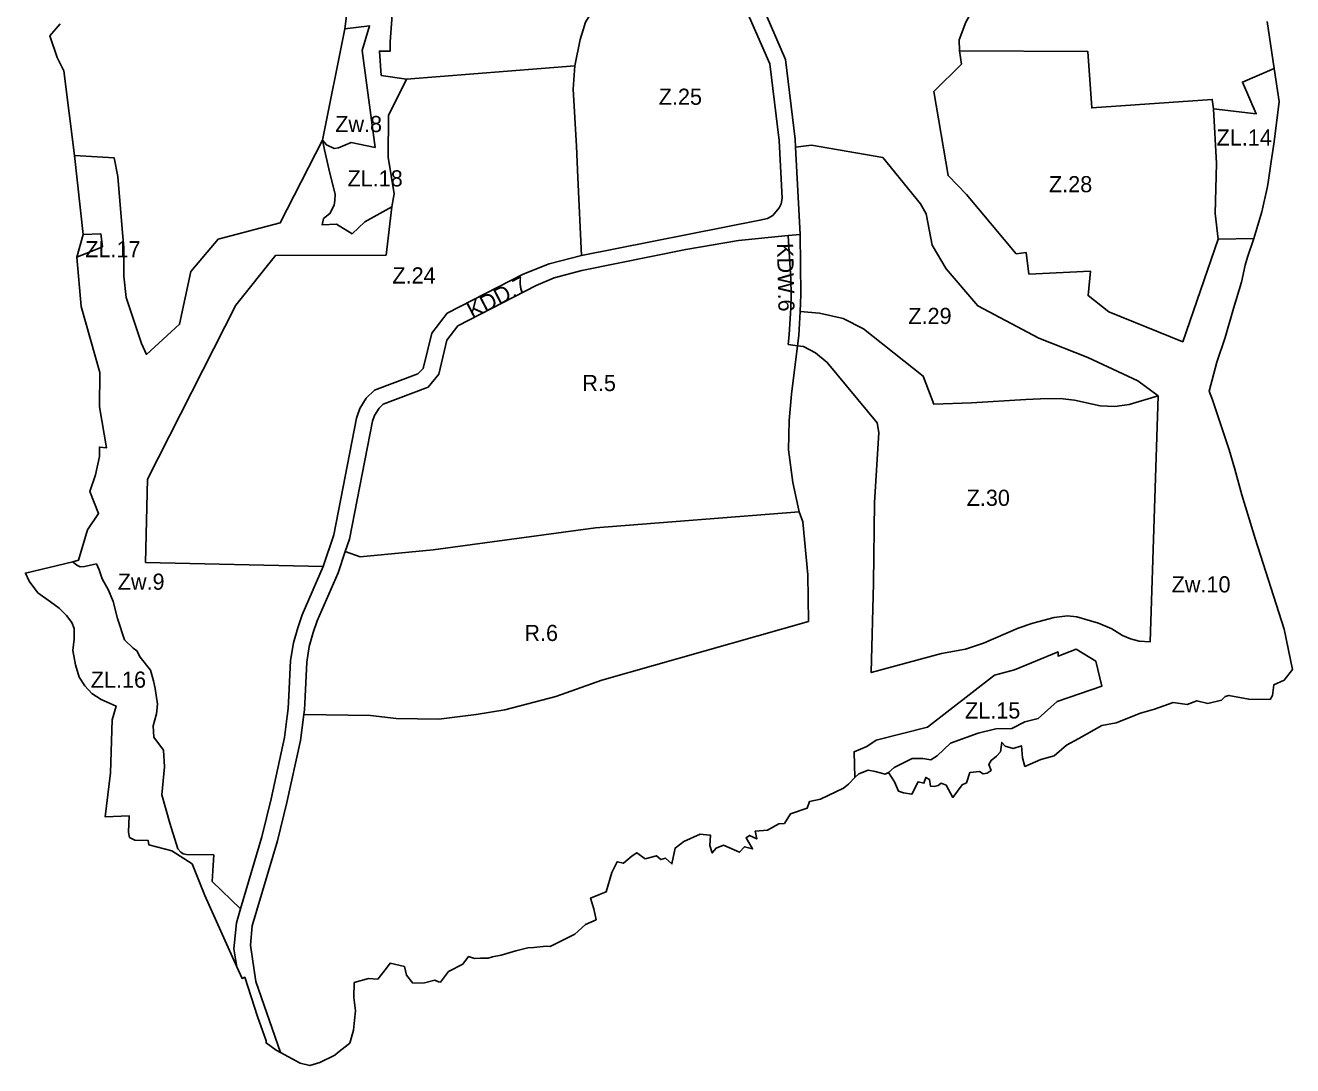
# Model space of a CAD drawing. Extents: x 7425478 to 7427982, y 5538517 to 5541171.
# Drawn here: x 7425675 to 7426459, y 5538517 to 5539161 of the extents above; entities that cross this region are included whole.
import ezdxf

# ---------------------------------------------------------------- set-up
doc = ezdxf.new("R2010")
doc.units = 0
doc.layers.add('linie_rozgraniczajace', color=7, linetype='Continuous')
doc.layers.add('oznaczenia_przeznaczen', color=7, linetype='Continuous')

msp = doc.modelspace()

# ---------------------------------------------------------------- linework, layer by layer
at = {"layer": 'linie_rozgraniczajace'}
for p, q in [((7425859.18, 5539089.77), (7425872.91, 5539158.79)), ((7425911.14, 5539127.51), (7426015.22, 5539135.71)), ((7426154.66, 5539031.49), (7426151.82, 5539085.48)), ((7426147.11, 5539030.69), (7426154.66, 5539031.49)), ((7426435.23, 5539028.98), (7426413.26, 5539028.54)), ((7425936.26, 5538982.64), (7425926.73, 5538970.31)), ((7425926.73, 5538970.31), (7425921.32, 5538948.42)), ((7425942.82, 5538974.77), (7425935.98, 5538965.92)), ((7425935.98, 5538965.92), (7425931.11, 5538944.9)), ((7426152.98, 5538962.54), (7426147.13, 5538963.32)), ((7425880.19, 5538917.77), (7425866.07, 5538845.42)), ((7425890, 5538915.88), (7425875.76, 5538842.86)), ((7426027.99, 5538849.76), (7426153.92, 5538859.85)), ((7426156.21, 5538853.5), (7426159.35, 5538820.71)), ((7425859.47, 5538825.87), (7425866.07, 5538845.42)), ((7425873.21, 5538835.3), (7425875.76, 5538842.86)), ((7425859.47, 5538825.87), (7425749.66, 5538828.37)), ((7425859.47, 5538825.87), (7425846.55, 5538796)), ((7426031.95, 5538755.64), (7426159.86, 5538791.87)), ((7425804.34, 5538589.28), (7425806.18, 5538578.12)), ((7425814.58, 5538591.46), (7425817.8, 5538569.09))]:
    msp.add_line(p, q, dxfattribs=at)
for points in [[(7425911.14, 5539127.51), (7425895.48, 5539129.82), (7425894.29, 5539144.9), (7425900.95, 5539144.83), (7425900.94, 5539150.62), (7425903, 5539178.71), (7425906.76, 5539195.32), (7425905.22, 5539195.17), (7425905.53, 5539201.35), (7425907.43, 5539202.47), (7425907.2, 5539235.15), (7425911.58, 5539260.65), (7425914.39, 5539273.74), (7425914.83, 5539278)], [(7425872.91, 5539158.79), (7425876.32, 5539186.72), (7425886.84, 5539193.05), (7425892.12, 5539214.17), (7425886.62, 5539235.46), (7425884.02, 5539237.65), (7425887.14, 5539253.37)], [(7426019.32, 5539018.32), (7426129.7, 5539040.2), (7426134.42, 5539041.34), (7426137.76, 5539043.2), (7426141.67, 5539047.91), (7426142.89, 5539050.48), (7426143.53, 5539053.88), (7426141.59, 5539089.62), (7426135.87, 5539137), (7426107.86, 5539201.24), (7426107.49, 5539204.41)], [(7426015.22, 5539135.71), (7426018.42, 5539151.99), (7426020.29, 5539158.01), (7426021.79, 5539162.83), (7426028.53, 5539173.75), (7426030.01, 5539177.46), (7426037.1, 5539195.25), (7426056.56, 5539197.78)], [(7426151.82, 5539085.48), (7426151.56, 5539090.49), (7426145.63, 5539139.65), (7426133.53, 5539167.33)], [(7426253.18, 5539145.1), (7426253, 5539151.86), (7426257.18, 5539162.75), (7426261.32, 5539170.23)], [(7426443.46, 5539163.33), (7426447.85, 5539134.04), (7426450.91, 5539113.67), (7426447.92, 5539088.66), (7426445.9, 5539076.62), (7426444.32, 5539064.93), (7426443.79, 5539061.12), (7426440.3, 5539045.47), (7426435.23, 5539028.98), (7426431.35, 5539017.43), (7426429.99, 5539012.34), (7426427.7, 5539001.83), (7426422.65, 5538985.66), (7426417.55, 5538967.6), (7426412.39, 5538952.44), (7426407.67, 5538934.46), (7426409.7, 5538929.17), (7426420.11, 5538898.03), (7426423.47, 5538886.22), (7426427.76, 5538870.31), (7426436.04, 5538843.26), (7426454.02, 5538787.09), (7426459.29, 5538762.25), (7426454.03, 5538755.63), (7426447.57, 5538752.58), (7426446.91, 5538746.11), (7426445.33, 5538743.66), (7426432.13, 5538743.75), (7426419.89, 5538746.15), (7426417.48, 5538745.41), (7426415.23, 5538743.28), (7426406.81, 5538741.13), (7426400.07, 5538742.8), (7426394.04, 5538740.55), (7426385.47, 5538741.75), (7426373.9, 5538737.61), (7426365.15, 5538735.14), (7426350.18, 5538729.16), (7426341.17, 5538727.45), (7426326.95, 5538719.43), (7426319.39, 5538715.34), (7426311.77, 5538708.71), (7426303.46, 5538706.39), (7426293.63, 5538702.2), (7426292.22, 5538707.54), (7426291.64, 5538714.86), (7426286.28, 5538713.2), (7426281.52, 5538714.62), (7426279.31, 5538717.05), (7426278.53, 5538711.14), (7426276.03, 5538708.57), (7426272.83, 5538705.92), (7426271.28, 5538703.42), (7426272.77, 5538699.68), (7426270.35, 5538697.94), (7426267.85, 5538697.69), (7426265.48, 5538698.95), (7426259.49, 5538698.37), (7426257.47, 5538692.04), (7426254.79, 5538690.79), (7426249.11, 5538683.04), (7426245.03, 5538690.51), (7426241.78, 5538691.91), (7426240.01, 5538690.47), (7426237.45, 5538689.8), (7426235.3, 5538689.88), (7426234.54, 5538694.15), (7426232.26, 5538695.33), (7426231.17, 5538691.81), (7426227.56, 5538692.56), (7426223.72, 5538685.04), (7426218.6, 5538685.86), (7426215.42, 5538686.88), (7426213.03, 5538692.56), (7426209.32, 5538698.44), (7426207.21, 5538697.45), (7426200.96, 5538699.01), (7426196.67, 5538699.95), (7426190.85, 5538697.62), (7426188.45, 5538695.35), (7426184.6, 5538691.16), (7426181.32, 5538688.82), (7426167.11, 5538681.94), (7426160.43, 5538680.55), (7426158.91, 5538676.31), (7426148.66, 5538672.8), (7426144.9, 5538666.82), (7426141.41, 5538666.58), (7426134.36, 5538662.81), (7426126.83, 5538662.02), (7426127.74, 5538657.3), (7426123.36, 5538659.45), (7426121.17, 5538658.01), (7426125.12, 5538651.14), (7426120.22, 5538652.5), (7426116.98, 5538649.08), (7426107.25, 5538653.46), (7426102.61, 5538651.59), (7426100.25, 5538648.6), (7426098.67, 5538653.28), (7426099.1, 5538659.71), (7426098.52, 5538659.7), (7426092.74, 5538660.26), (7426082.71, 5538655.67), (7426077.21, 5538651.62), (7426075.22, 5538641.79), (7426071.22, 5538645.46), (7426068.34, 5538644.55), (7426065.64, 5538646.9), (7426058.63, 5538644.95), (7426053.64, 5538648.74), (7426050.64, 5538646.83), (7426045.22, 5538642.28), (7426041.38, 5538643.23), (7426038.19, 5538636.52), (7426034.61, 5538624.66), (7426030.42, 5538622.81), (7426024.92, 5538620.72), (7426026.96, 5538614.06), (7426028.31, 5538607.27), (7426021.88, 5538604.37), (7426015.15, 5538598.31), (7426000.04, 5538590.75), (7425997.47, 5538590.85), (7425989.86, 5538590.05), (7425986.13, 5538590), (7425978.71, 5538587.95), (7425969.55, 5538585.41), (7425964.23, 5538584.42), (7425961.49, 5538583.47), (7425956.88, 5538583.51), (7425953.16, 5538583.39), (7425949.49, 5538584.59), (7425945.84, 5538579.76), (7425937.15, 5538575.35), (7425932.11, 5538568.74), (7425930.87, 5538568.76), (7425928.54, 5538569.87), (7425922.1, 5538568.19), (7425915.08, 5538568.1), (7425911.07, 5538572.97), (7425909.75, 5538578.29), (7425900.86, 5538580.37), (7425898.7, 5538577.37), (7425893.34, 5538570.56), (7425887.59, 5538570.99), (7425878.78, 5538568.43), (7425878.56, 5538559.26), (7425879.51, 5538550.92), (7425878.96, 5538545.1), (7425878.37, 5538538.9), (7425875.92, 5538530.9), (7425868.3, 5538524.99), (7425866.72, 5538523.54), (7425857.43, 5538518.9), (7425851.26, 5538516.97), (7425845.26, 5538518.54), (7425833.16, 5538525.12), (7425830.36, 5538526.64), (7425824.19, 5538531.06), (7425824.2, 5538532.44), (7425818.96, 5538547.35), (7425811.03, 5538571.65), (7425809.43, 5538570.89), (7425806.18, 5538578.12), (7425786.3, 5538622.32), (7425778.39, 5538641.84), (7425765.93, 5538650), (7425751.56, 5538653.72), (7425751.15, 5538656.41), (7425742.94, 5538656.47), (7425739.76, 5538658.25), (7425739.03, 5538661.42), (7425739.42, 5538671.64), (7425724.74, 5538670.95), (7425727.93, 5538698.3), (7425729, 5538731.02), (7425731.43, 5538739.49), (7425722.1, 5538743.61), (7425716.31, 5538747.22), (7425711.97, 5538752.1), (7425708.56, 5538757.37), (7425706.35, 5538764.97), (7425704.65, 5538773.98), (7425705.47, 5538780.92), (7425705.44, 5538787.5), (7425704.09, 5538791.26), (7425700.72, 5538795.51), (7425696.24, 5538800.06), (7425690.89, 5538804.11), (7425683.06, 5538809.65), (7425677.69, 5538816.74), (7425675.26, 5538821.86), (7425704.73, 5538828.9), (7425708.22, 5538829.74), (7425713.76, 5538848.69), (7425720.56, 5538858.73), (7425715.25, 5538872.42), (7425718.63, 5538882.67), (7425721.05, 5538893.94), (7425721.1, 5538899.78), (7425725.56, 5538899.39), (7425721.22, 5538924.65), (7425721.38, 5538946.03), (7425709.87, 5538986.76), (7425707.21, 5539017.36), (7425711.13, 5539031.37), (7425705.65, 5539080.27), (7425699.02, 5539132.75), (7425694.94, 5539141.04), (7425690.44, 5539154.31), (7425696.83, 5539161.76)], [(7425859.18, 5539089.77), (7425861.54, 5539086.83), (7425866.22, 5539084.64), (7425869, 5539085.07), (7425876.77, 5539088.38), (7425891.66, 5539085.34), (7425883.6, 5539145.37), (7425888.24, 5539160.57), (7425872.91, 5539158.79)], [(7426253.18, 5539145.1), (7426254.32, 5539136.91), (7426237.34, 5539119.85), (7426246.12, 5539067.9), (7426257.55, 5539056.13), (7426288.3, 5539019.45), (7426294.49, 5539020.16), (7426296.11, 5539006.95), (7426334.17, 5539008.74), (7426332.78, 5538993.63), (7426345.61, 5538983.46), (7426391.3, 5538965.02), (7426413.26, 5539028.54)], [(7426410.28, 5539109.1), (7426409.55, 5539115.02), (7426334.99, 5539109.74), (7426332.51, 5539144.71), (7426253.18, 5539145.1)], [(7426019.32, 5539018.32), (7426017.04, 5539066.58), (7426016.16, 5539086.04), (7426014.23, 5539121.39), (7426015.22, 5539135.71)], [(7426447.85, 5539134.04), (7426428.21, 5539125.71), (7426436.79, 5539106.12), (7426410.28, 5539109.1)], [(7425902.09, 5539048.48), (7425903.42, 5539056.67), (7425899.67, 5539079.17), (7425899.97, 5539105.06), (7425911.14, 5539127.51)], [(7426410.28, 5539109.1), (7426412.13, 5539075.3), (7426411.31, 5539044.49), (7426413.26, 5539028.54)], [(7425705.65, 5539080.27), (7425730.17, 5539078.86), (7425732.54, 5539067.34), (7425735.36, 5539032.35), (7425736.11, 5539023.35), (7425736.2, 5539005.52), (7425737.62, 5538992.32), (7425747.17, 5538964.02), (7425750.13, 5538957.21), (7425770.72, 5538975.83), (7425777.56, 5539008.6), (7425794.45, 5539028.42), (7425832.95, 5539038.53), (7425859.18, 5539089.77)], [(7425859.18, 5539089.77), (7425860.27, 5539083.78), (7425862.99, 5539071.98), (7425866.93, 5539056.23), (7425866.67, 5539052.35), (7425866.22, 5539049.52), (7425863.65, 5539044.32), (7425859.69, 5539041.25), (7425858.98, 5539037.37), (7425867.85, 5539037.73), (7425877.43, 5539031.86), (7425885.34, 5539039.27), (7425902.09, 5539048.48)], [(7426151.82, 5539085.48), (7426161.56, 5539086.75), (7426205.65, 5539079.01), (7426229.1, 5539050.44), (7426232.57, 5539044.28), (7426236.33, 5539024.78), (7426244.99, 5539010.06), (7426264.5, 5538987.23), (7426302.2, 5538967.22), (7426332.48, 5538955.3), (7426363.56, 5538940.75), (7426376.1, 5538931.45)], [(7425902.09, 5539048.48), (7425898.46, 5539018.63), (7425829.97, 5539018.32), (7425805.47, 5538987.75), (7425750.85, 5538879.92), (7425749.66, 5538828.37)], [(7425711.13, 5539031.37), (7425722.03, 5539031.77), (7425722.89, 5539023.8), (7425707.21, 5539017.36)], [(7426154.71, 5538983.82), (7426154.97, 5538994.24), (7426154.66, 5539031.49)], [(7425942.82, 5538974.77), (7425991.27, 5538999.79), (7426002.33, 5539004.6), (7426019.45, 5539009.12), (7426083.86, 5539022.18), (7426116.54, 5539027.69), (7426147.11, 5539030.69)], [(7426147.11, 5539030.69), (7426148.89, 5539003.85), (7426148.97, 5538994.35), (7426148.82, 5538986.11), (7426147.9, 5538969.36), (7426147.13, 5538963.32)], [(7425936.26, 5538982.64), (7425983.15, 5539006.85), (7425999.34, 5539013.34), (7426019.32, 5539018.32)], [(7426152.98, 5538962.54), (7426153.87, 5538968.82), (7426154.71, 5538983.82)], [(7426376.1, 5538931.45), (7426358.2, 5538926.23), (7426349.24, 5538924.86), (7426340.21, 5538925.36), (7426324.3, 5538928.78), (7426315.43, 5538929.94), (7426303.36, 5538929.61), (7426294.14, 5538929.35), (7426260.54, 5538927.18), (7426237.25, 5538926.45), (7426230.74, 5538943.79), (7426193.7, 5538973.11), (7426181.16, 5538979.49), (7426166.51, 5538982.81), (7426154.71, 5538983.82)], [(7426153.92, 5538859.85), (7426150.07, 5538877.91), (7426147.42, 5538898.04), (7426147.75, 5538916.22), (7426149.3, 5538932.56), (7426152.98, 5538962.54)], [(7426376.1, 5538931.45), (7426371.18, 5538779.32), (7426364.43, 5538779.8), (7426358.89, 5538781.12), (7426354.03, 5538783.13), (7426347.52, 5538787.25), (7426339.16, 5538790.91), (7426325.71, 5538794.84), (7426319.91, 5538795.33), (7426311.7, 5538794.34), (7426298.64, 5538790.92), (7426289.43, 5538787.71), (7426268.12, 5538778.53), (7426256.89, 5538774.67), (7426242.09, 5538772.04), (7426198.54, 5538760.25), (7426199.91, 5538815.58), (7426200.67, 5538865.47), (7426203.27, 5538908.85), (7426202.26, 5538914.85), (7426171.36, 5538952.14), (7426164.13, 5538958.06), (7426156.69, 5538962.05), (7426152.98, 5538962.54)], [(7425880.19, 5538917.77), (7425880.47, 5538918.93), (7425882.28, 5538923.75), (7425886.21, 5538930.13), (7425891.21, 5538935.02), (7425918.17, 5538945.26), (7425921.32, 5538948.42)], [(7425890, 5538915.88), (7425891.3, 5538919.33), (7425894.08, 5538923.84), (7425896.62, 5538926.33), (7425924.41, 5538936.83), (7425931.11, 5538944.9)], [(7426153.92, 5538859.85), (7426156.21, 5538853.5)], [(7426027.99, 5538849.76), (7425927.46, 5538836.21), (7425882.4, 5538831.8)], [(7425847.55, 5538734.33), (7425847.92, 5538737.17), (7425848.32, 5538745.37), (7425849.36, 5538766.63), (7425850.95, 5538776.45), (7425853.32, 5538785.08), (7425855.88, 5538792.38), (7425868.69, 5538821.92), (7425873.21, 5538835.3)], [(7425882.4, 5538831.8), (7425873.21, 5538835.3)], [(7425704.73, 5538828.9), (7425704.89, 5538828.66), (7425707.12, 5538826.67), (7425709.2, 5538825.76), (7425711.82, 5538825.89), (7425719.2, 5538827.59)], [(7425808.39, 5538614.12), (7425790.88, 5538630.86), (7425791.86, 5538647.41), (7425775.06, 5538647.71), (7425772.95, 5538648.14), (7425771.37, 5538649.14), (7425769.63, 5538651.18), (7425764.7, 5538667.08), (7425759.8, 5538684.51), (7425761.33, 5538701.87), (7425760.67, 5538712.24), (7425754.75, 5538720.38), (7425754.38, 5538727.4), (7425756.42, 5538734.7), (7425756.92, 5538740.68), (7425755.6, 5538750.47), (7425754.46, 5538755.1), (7425752.6, 5538761.76), (7425746.26, 5538769.88), (7425744.31, 5538773.64), (7425741.99, 5538775.29), (7425736.64, 5538780.6), (7425732.3, 5538793.65), (7425729.57, 5538804.34), (7425726.76, 5538811.17), (7425722.85, 5538818.31), (7425720.99, 5538823.79), (7425719.2, 5538827.59)], [(7426159.35, 5538820.71), (7426159.86, 5538791.87)], [(7425846.55, 5538796), (7425843.77, 5538788.05), (7425841.17, 5538778.57), (7425839.4, 5538767.67), (7425838.34, 5538745.86), (7425837.95, 5538738.07), (7425837.31, 5538733.2)], [(7426188.45, 5538695.35), (7426187.96, 5538711.29), (7426195.92, 5538714.45), (7426201.64, 5538718.42), (7426233.39, 5538726.45), (7426274.74, 5538758.71), (7426287.26, 5538761.94), (7426314.16, 5538773.08), (7426314.15, 5538770.51), (7426325.41, 5538774.84), (7426337.48, 5538767.28), (7426341.14, 5538751.81), (7426313.56, 5538742.44), (7426301.81, 5538731.75), (7426293.57, 5538729.71), (7426285.59, 5538725.59), (7426275.7, 5538725.51), (7426264.68, 5538722.68), (7426247.58, 5538716.6), (7426239.29, 5538708.64), (7426235.5, 5538706.28), (7426230.56, 5538707.09), (7426223.97, 5538707.16), (7426212.69, 5538701.53), (7426209.32, 5538698.44)], [(7425847.55, 5538734.33), (7425888.72, 5538733.66), (7425904.68, 5538731.92), (7425931.06, 5538731.51), (7425954.12, 5538734.26), (7425971.95, 5538737.26), (7426003.54, 5538745.52), (7426031.95, 5538755.64)], [(7425837.31, 5538733.2), (7425835.58, 5538720.04), (7425827.31, 5538682.18), (7425821.56, 5538658.7), (7425808.39, 5538614.12)], [(7425847.55, 5538734.33), (7425845.44, 5538718.32), (7425837.05, 5538679.92), (7425831.21, 5538656.09), (7425815.67, 5538603.46), (7425814.58, 5538591.46)], [(7425808.39, 5538614.12), (7425805.8, 5538605.34), (7425804.34, 5538589.28)], [(7425833.16, 5538525.12), (7425817.8, 5538569.09)]]:
    msp.add_lwpolyline(points, dxfattribs=at)

# ---------------------------------------------------------------- texts
at = {"layer": 'oznaczenia_przeznaczen'}
for s, p in [('Z.25', (7426067.11, 5539111.67)), ('Zw.8', (7425866.97, 5539094.78)), ('ZL.14', (7426412.23, 5539086.43)), ('ZL.18', (7425874.56, 5539061.14)), ('Z.28', (7426308.53, 5539057.55)), ('ZL.17', (7425712.31, 5539017.3)), ('Z.24', (7425902.33, 5539001.07)), ('Z.29', (7426221.53, 5538976.01)), ('R.5', (7426019.82, 5538934.48)), ('Z.30', (7426257.6, 5538863.45)), ('Zw.9', (7425732.41, 5538811.52)), ('Zw.10', (7426384.43, 5538809.89)), ('R.6', (7425984, 5538779.8)), ('ZL.16', (7425715.74, 5538750.9)), ('ZL.15', (7426256.6, 5538731.83))]:
    msp.add_text(s, height=10, dxfattribs=at).set_placement(p)
for s, rotation, p in [('KDW.6', 271.30548, (7426140.24, 5539025.96)), ('KDD.7', 27.57654, (7425951.86, 5538978.97))]:
    msp.add_text(s, height=10, rotation=rotation, dxfattribs=at).set_placement(p)

doc.saveas('drawing.dxf')
